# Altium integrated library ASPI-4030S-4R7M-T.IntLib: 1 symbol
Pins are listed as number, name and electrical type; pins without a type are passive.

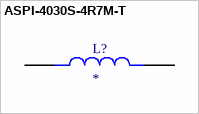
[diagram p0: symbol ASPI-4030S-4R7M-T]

## ASPI-4030S-4R7M-T
designator L?
4.7 ÂµH Shielded Drum Core, Wirewound Inductor 2 A 60mOhm Nonstandard; MP: ASPI-4030S-4R7M-T; MF: Abracon LLC
footprint IND_ASPI-4030S-4R7M-T
pins: 1, 2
